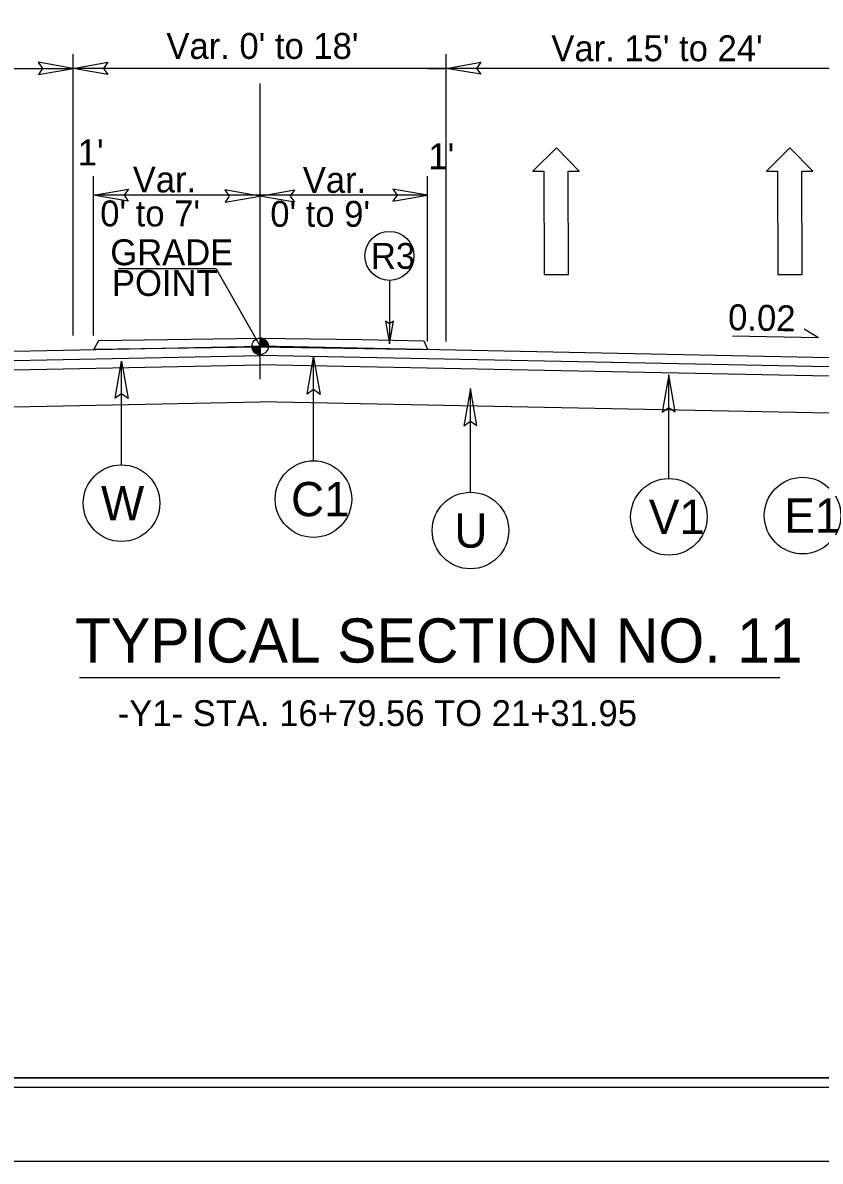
# Model space of a CAD drawing. Extents: x 1640342 to 1730599, y 538663 to 843747.
# Drawn here: x 1730008.1 to 1730051.2, y 539149.8 to 539211.3 of the extents above; entities that cross this region are included whole.
import ezdxf

# ---------------------------------------------------------------- set-up
doc = ezdxf.new("R2010")
doc.units = 0
for name, color, linetype in [('Default', 7, 'Continuous'), ('Sheet Clip Boundary CELL', 7, 'Continuous'), ('Sheet Layout Plan Border', 7, 'Continuous'), ('Sheet Plan CELL', 7, 'Continuous'), ('Sheet Plan Layout CELL', 7, 'Continuous'), ('Sheet Plot Border Inside CELL', 7, 'Continuous'), ('Sheet Plot Border Outside CELL', 7, 'Continuous'), ('Typical Grade Point Symbol CELL', 7, 'Continuous'), ('Typical ID Circle CELL', 7, 'Continuous'), ('Typical Pavement Slope CELL', 7, 'Continuous'), ('Typical Pavement Slope Information CELL', 7, 'Continuous'), ('Typical Terminator CELL', 7, 'Continuous'), ('Typical Text Centerline CELL', 7, 'Continuous'), ('Typical Text Grade Point CELL', 7, 'Continuous'), ('Typical Text ID Circle CELL', 7, 'Continuous'), ('Typical Text Label CELL', 7, 'Continuous')]:
    doc.layers.add(name, color=color, linetype=linetype)

msp = doc.modelspace()

# ---------------------------------------------------------------- linework, layer by layer
at = {"layer": 'Default'}
for p, q in [((1730010.789, 539199.996), (1730010.789, 539209.631)), ((1730030.975, 539194.101), (1730030.975, 539209.631)), ((1730002.913, 539208.855), (1730010.789, 539208.863)), ((1730024.913, 539208.867), (1730010.789, 539208.867)), ((1730042.975, 539208.867), (1730024.913, 539208.867)), ((1730029.975, 539208.867), (1730025.934, 539208.867)), ((1730054.913, 539208.867), (1730042.975, 539208.867)), ((1730036.942, 539204.57), (1730035.666, 539203.307)), ((1730038.184, 539203.314), (1730036.942, 539204.57)), ((1730049.584, 539204.57), (1730048.308, 539203.307)), ((1730050.826, 539203.314), (1730049.584, 539204.57)), ((1730035.666, 539203.307), (1730036.266, 539203.309)), ((1730036.266, 539203.309), (1730036.282, 539197.713)), ((1730037.585, 539203.313), (1730038.184, 539203.314)), ((1730037.601, 539197.717), (1730037.585, 539203.313)), ((1730048.308, 539203.307), (1730048.908, 539203.309)), ((1730048.908, 539203.309), (1730048.924, 539197.713)), ((1730050.227, 539203.313), (1730050.826, 539203.314)), ((1730050.243, 539197.717), (1730050.227, 539203.313)), ((1730029.975, 539202.006), (1730011.905, 539202.006)), ((1730010.789, 539194.423), (1730010.789, 539199.996)), ((1730036.282, 539197.713), (1730037.601, 539197.717)), ((1730048.924, 539197.713), (1730050.243, 539197.717))]:
    msp.add_line(p, q, dxfattribs=at)
for points in [[(1730008.915, 539208.54), (1730010.789, 539208.863), (1730008.905, 539209.196), (1730009.144, 539208.863)], [(1730012.663, 539208.54), (1730010.789, 539208.863), (1730012.674, 539209.196), (1730012.434, 539208.863)], [(1730032.85, 539208.544), (1730030.975, 539208.867), (1730032.86, 539209.2), (1730032.621, 539208.867)], [(1730013.78, 539201.683), (1730011.905, 539202.006), (1730013.79, 539202.339), (1730013.551, 539202.006)], [(1730019.015, 539201.636), (1730020.889, 539201.958), (1730019.005, 539202.292), (1730019.244, 539201.958)], [(1730022.764, 539201.636), (1730020.889, 539201.958), (1730022.774, 539202.292), (1730022.535, 539201.958)], [(1730028.101, 539201.683), (1730029.975, 539202.006), (1730028.091, 539202.339), (1730028.33, 539202.006)], [(1730029.989, 539193.657), (1730029.791, 539194.124), (1730026.438, 539194.194), (1730020.87, 539194.259), (1730012.164, 539194.134), (1730011.921, 539193.675), (1730020.87, 539193.811)]]:
    msp.add_lwpolyline(points, close=True, dxfattribs=at)
at = {"layer": 'Sheet Clip Boundary CELL'}
msp.add_lwpolyline([(1729883.99, 539154.279), (1730163.993, 539154.279), (1730163.993, 539321.981), (1730126.14, 539321.981), (1730126.14, 539364.279), (1729883.99, 539364.279)], close=True, dxfattribs=at)
at = {"layer": 'Sheet Layout Plan Border'}
msp.add_lwpolyline([(1729883.99, 539154.279), (1730163.993, 539154.279), (1730163.993, 539321.981), (1730126.14, 539321.981), (1730126.14, 539364.279), (1729883.99, 539364.279)], close=True, dxfattribs=at)
at = {"layer": 'Sheet Plan CELL'}
for points in [[(1729873.99, 539154.279), (1729873.985, 539364.274), (1730133.983, 539364.281), (1730133.985, 539334.269), (1730173.993, 539334.266), (1730173.993, 539154.279)], [(1730173.998, 539364.279), (1729873.99, 539364.279), (1729873.99, 539154.279), (1730173.993, 539154.279)]]:
    msp.add_lwpolyline(points, close=True, dxfattribs=at)
at = {"layer": 'Sheet Plan Layout CELL'}
msp.add_lwpolyline([(1729873.985, 539364.274), (1729873.99, 539154.279), (1730173.99, 539154.279), (1730173.99, 539321.981), (1730126.14, 539321.981), (1730126.14, 539364.279)], close=True, dxfattribs=at)
at = {"layer": 'Sheet Plot Border Inside CELL'}
msp.add_lwpolyline([(1729843.293, 539153.776), (1730176.49, 539153.779), (1730176.493, 539364.776), (1729843.293, 539364.776)], close=True, dxfattribs=at)
at = {"layer": 'Sheet Plot Border Outside CELL'}
msp.add_lwpolyline([(1729840.693, 539149.776), (1730177.393, 539149.776), (1730177.393, 539368.776), (1729840.693, 539368.776)], close=True, dxfattribs=at)
at = {"layer": 'Typical Grade Point Symbol CELL'}
for p, q in [((1730020.466, 539193.839), (1730020.913, 539193.839)), ((1730020.912, 539193.391), (1730020.913, 539193.839)), ((1730020.913, 539193.839), (1730020.912, 539193.391)), ((1730020.913, 539193.839), (1730020.913, 539194.286)), ((1730021.36, 539193.839), (1730020.913, 539193.839))]:
    msp.add_line(p, q, dxfattribs=at)
for points in [[(1730020.468, 539193.839), (1730020.468, 539193.79)], [(1730020.477, 539193.839), (1730020.477, 539193.737)], [(1730020.485, 539193.839), (1730020.485, 539193.705)], [(1730020.494, 539193.839), (1730020.494, 539193.679)], [(1730020.503, 539193.839), (1730020.503, 539193.658)], [(1730020.512, 539193.839), (1730020.512, 539193.639)], [(1730020.521, 539193.839), (1730020.521, 539193.622)], [(1730020.53, 539193.839), (1730020.53, 539193.606)], [(1730020.539, 539193.839), (1730020.539, 539193.592)], [(1730020.548, 539193.839), (1730020.548, 539193.579)], [(1730020.557, 539193.839), (1730020.557, 539193.567)], [(1730020.566, 539193.839), (1730020.566, 539193.556)], [(1730020.575, 539193.839), (1730020.575, 539193.545)], [(1730020.584, 539193.839), (1730020.584, 539193.535)], [(1730020.593, 539193.839), (1730020.593, 539193.525)], [(1730020.602, 539193.839), (1730020.602, 539193.517)], [(1730020.611, 539193.839), (1730020.611, 539193.509)], [(1730020.62, 539193.839), (1730020.62, 539193.501)], [(1730020.629, 539193.839), (1730020.629, 539193.493)], [(1730020.638, 539193.839), (1730020.638, 539193.486)], [(1730020.647, 539193.839), (1730020.647, 539193.479)], [(1730020.655, 539193.839), (1730020.655, 539193.473)], [(1730020.664, 539193.839), (1730020.664, 539193.467)], [(1730020.673, 539193.839), (1730020.673, 539193.461)], [(1730020.682, 539193.839), (1730020.682, 539193.455)], [(1730020.691, 539193.839), (1730020.691, 539193.45)], [(1730020.7, 539193.839), (1730020.7, 539193.445)], [(1730020.709, 539193.839), (1730020.709, 539193.44)], [(1730020.718, 539193.839), (1730020.718, 539193.436)], [(1730020.727, 539193.839), (1730020.727, 539193.432)], [(1730020.736, 539193.839), (1730020.736, 539193.428)], [(1730020.745, 539193.839), (1730020.745, 539193.424)], [(1730020.754, 539193.839), (1730020.754, 539193.42)], [(1730020.763, 539193.839), (1730020.763, 539193.417)], [(1730020.772, 539193.839), (1730020.772, 539193.414)], [(1730020.781, 539193.839), (1730020.781, 539193.411)], [(1730020.79, 539193.839), (1730020.79, 539193.409)], [(1730020.799, 539193.839), (1730020.799, 539193.406)], [(1730020.808, 539193.839), (1730020.808, 539193.404)], [(1730020.816, 539193.839), (1730020.816, 539193.402)], [(1730020.825, 539193.839), (1730020.825, 539193.4)], [(1730020.834, 539193.839), (1730020.834, 539193.398)], [(1730020.843, 539193.839), (1730020.843, 539193.397)], [(1730020.852, 539193.839), (1730020.852, 539193.395)], [(1730020.861, 539193.839), (1730020.861, 539193.394)], [(1730020.87, 539193.839), (1730020.87, 539193.393)], [(1730020.879, 539193.839), (1730020.879, 539193.392)], [(1730020.888, 539193.839), (1730020.888, 539193.392)], [(1730020.897, 539193.839), (1730020.897, 539193.391)], [(1730020.906, 539193.839), (1730020.906, 539193.391), (1730020.906, 539193.391)], [(1730020.917, 539194.286), (1730020.917, 539194.286), (1730020.917, 539193.839)], [(1730020.926, 539194.286), (1730020.926, 539193.839)], [(1730020.935, 539194.285), (1730020.935, 539193.839)], [(1730020.944, 539194.285), (1730020.944, 539193.839)], [(1730020.953, 539194.284), (1730020.953, 539193.839)], [(1730020.962, 539194.283), (1730020.962, 539193.839)], [(1730020.97, 539194.282), (1730020.97, 539193.839)], [(1730020.979, 539194.281), (1730020.979, 539193.839)], [(1730020.988, 539194.28), (1730020.988, 539193.839)], [(1730020.997, 539194.278), (1730020.997, 539193.839)], [(1730021.006, 539194.276), (1730021.006, 539193.839)], [(1730021.015, 539194.274), (1730021.015, 539193.839)], [(1730021.024, 539194.272), (1730021.024, 539193.839)], [(1730021.033, 539194.269), (1730021.033, 539193.839)], [(1730021.042, 539194.267), (1730021.042, 539193.839)], [(1730021.051, 539194.264), (1730021.051, 539193.839)], [(1730021.06, 539194.261), (1730021.06, 539193.839)], [(1730021.069, 539194.258), (1730021.069, 539193.839)], [(1730021.078, 539194.254), (1730021.078, 539193.839)], [(1730021.087, 539194.25), (1730021.087, 539193.839)], [(1730021.096, 539194.246), (1730021.096, 539193.839)], [(1730021.105, 539194.242), (1730021.105, 539193.839)], [(1730021.114, 539194.238), (1730021.114, 539193.839)], [(1730021.123, 539194.233), (1730021.123, 539193.839)], [(1730021.131, 539194.228), (1730021.131, 539193.839)], [(1730021.14, 539194.223), (1730021.14, 539193.839)], [(1730021.149, 539194.218), (1730021.149, 539193.839)], [(1730021.158, 539194.212), (1730021.158, 539193.839)], [(1730021.167, 539194.206), (1730021.167, 539193.839)], [(1730021.176, 539194.199), (1730021.176, 539193.839)], [(1730021.185, 539194.193), (1730021.185, 539193.839)], [(1730021.194, 539194.186), (1730021.194, 539193.839)], [(1730021.203, 539194.178), (1730021.203, 539193.839)], [(1730021.212, 539194.171), (1730021.212, 539193.839)], [(1730021.221, 539194.163), (1730021.221, 539193.839)], [(1730021.23, 539194.154), (1730021.23, 539193.839)], [(1730021.239, 539194.145), (1730021.239, 539193.839)], [(1730021.248, 539194.135), (1730021.248, 539193.839)], [(1730021.257, 539194.124), (1730021.257, 539193.839)], [(1730021.266, 539194.113), (1730021.266, 539193.839)], [(1730021.275, 539194.101), (1730021.275, 539193.839)], [(1730021.284, 539194.088), (1730021.284, 539193.839)], [(1730021.293, 539194.074), (1730021.293, 539193.839)], [(1730021.301, 539194.059), (1730021.301, 539193.839)], [(1730021.31, 539194.043), (1730021.31, 539193.839)], [(1730021.319, 539194.024), (1730021.319, 539193.839)], [(1730021.328, 539194.004), (1730021.328, 539193.839)], [(1730021.337, 539193.979), (1730021.337, 539193.839)], [(1730021.346, 539193.948), (1730021.346, 539193.839)], [(1730021.355, 539193.902), (1730021.355, 539193.839)]]:
    msp.add_lwpolyline(points, dxfattribs=at)
msp.add_circle((1730020.912, 539193.839), 0.447, dxfattribs=at)
for start, end in [(179.99071, 269.99071), (359.99071, 89.99071)]:
    msp.add_arc((1730020.912, 539193.839), 0.447, start, end, dxfattribs=at)
at = {"layer": 'Typical ID Circle CELL'}
for p, q in [((1730023.797, 539187.648), (1730023.797, 539193.258)), ((1730013.413, 539187.428), (1730013.413, 539193.038)), ((1730043.034, 539186.689), (1730043.034, 539192.298)), ((1730032.297, 539185.948), (1730032.297, 539191.558))]:
    msp.add_line(p, q, dxfattribs=at)
for centre in [(1730013.414, 539185.358), (1730023.798, 539185.577), (1730043.033, 539184.618), (1730050.267, 539184.686), (1730032.296, 539183.877)]:
    msp.add_circle(centre, 2.071, dxfattribs=at)
at = {"layer": 'Typical Pavement Slope CELL'}
for p, q in [((1730029.975, 539208.867), (1730030.975, 539208.867)), ((1730011.905, 539194.423), (1730011.905, 539203.04)), ((1730029.975, 539194.101), (1730029.975, 539203.04)), ((1729997.069, 539193.362), (1730020.913, 539193.839)), ((1730054.975, 539193.157), (1730020.913, 539193.839)), ((1729997.07, 539192.862), (1730020.913, 539193.338)), ((1730054.975, 539192.657), (1730020.913, 539193.338)), ((1729997.07, 539192.361), (1730020.923, 539192.839)), ((1730053.475, 539192.187), (1730020.903, 539192.839)), ((1729997.072, 539190.362), (1730020.913, 539190.839)), ((1730053.476, 539190.187), (1730020.913, 539190.839))]:
    msp.add_line(p, q, dxfattribs=at)
at = {"layer": 'Typical Pavement Slope Information CELL'}
for q in [(1730050.345, 539194.768), (1730046.469, 539194.388)]:
    msp.add_line((1730051.128, 539194.295), q, dxfattribs=at)
at = {"layer": 'Typical Terminator CELL'}
for points in [[(1730023.452, 539191.25), (1730023.797, 539193.258), (1730024.154, 539191.239), (1730023.797, 539191.495)], [(1730013.067, 539191.03), (1730013.413, 539193.038), (1730013.77, 539191.019), (1730013.413, 539191.276)], [(1730043.38, 539190.291), (1730043.034, 539192.298), (1730042.677, 539190.279), (1730043.034, 539190.536)], [(1730032.643, 539189.55), (1730032.297, 539191.558), (1730031.94, 539189.539), (1730032.297, 539189.795)]]:
    msp.add_lwpolyline(points, close=True, dxfattribs=at)
at = {"layer": 'Typical Text Centerline CELL'}
msp.add_line((1730020.913, 539192.056), (1730020.913, 539208.056), dxfattribs=at)
at = {"layer": 'Typical Text Grade Point CELL'}
for q in [(1730013.237, 539198.029), (1730020.913, 539193.839)]:
    msp.add_line((1730018.54, 539198.029), q, dxfattribs=at)
at = {"layer": 'Typical Text ID Circle CELL'}
msp.add_line((1730027.91, 539197.399), (1730027.91, 539193.967), dxfattribs=at)
msp.add_lwpolyline([(1730027.698, 539195.197), (1730027.91, 539193.967), (1730028.128, 539195.204), (1730027.91, 539195.046)], close=True, dxfattribs=at)
msp.add_circle((1730027.91, 539198.726), 1.328, dxfattribs=at)
at = {"layer": 'Typical Text Label CELL'}
msp.add_line((1730011.143, 539175.938), (1730049.034, 539175.938), dxfattribs=at)

# ---------------------------------------------------------------- texts
at = {"layer": 'Typical Pavement Slope Information CELL'}
for s, p in [("Var. 0' to 18'", (1730015.84, 539209.378)), ("Var. 15' to 24'", (1730036.671, 539209.253)), ("1'", (1730011.045, 539203.622)), ("1'", (1730030.02, 539203.415)), ('Var.', (1730014.021, 539202.159)), ('Var.', (1730023.222, 539202.136)), (" 0' to 7'", (1730011.741, 539200.324)), (" 0' to 9'", (1730020.943, 539200.3))]:
    msp.add_text(s, height=1.4, dxfattribs=at).set_placement(p)
msp.add_text('0.02', height=1.4, rotation=358.85426, dxfattribs=at).set_placement((1730046.228, 539194.717))
at = {"layer": 'Typical Text Grade Point CELL'}
for s, p in [('GRADE', (1730012.804, 539198.223)), ('POINT', (1730012.895, 539196.564))]:
    msp.add_text(s, height=1.4, rotation=0.00023, dxfattribs=at).set_placement(p)
at = {"layer": 'Typical Text ID Circle CELL'}
for s, height, p in [('R3', 1.4, (1730026.909, 539198.026)), ('C1', 1.8535, (1730022.587, 539184.65)), ('W', 1.854, (1730012.301, 539184.431)), ('V1', 1.8535, (1730041.946, 539183.691)), ('E1', 1.8535, (1730049.28, 539183.759)), ('U', 1.854, (1730031.422, 539182.951))]:
    msp.add_text(s, height=height, dxfattribs=at).set_placement(p)
at = {"layer": 'Typical Text Label CELL'}
msp.add_text('TYPICAL SECTION NO. 11', height=2.38712, rotation=360, dxfattribs=at).set_placement((1730010.89, 539176.738))
msp.add_text('-Y1- STA. 16+79.56 TO 21+31.95', height=1.4, dxfattribs=at).set_placement((1730013.207, 539173.304))

doc.saveas('drawing.dxf')
